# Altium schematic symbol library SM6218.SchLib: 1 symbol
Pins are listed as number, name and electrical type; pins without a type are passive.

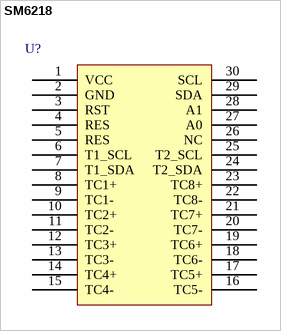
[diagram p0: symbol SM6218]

## SM6218
designator U?
footprint SM6218
pins: 1 VCC, 2 GND, 3 RST, 4 RES, 5 RES, 6 T1_SCL, 7 T1_SDA, 8 TC1+, 9 TC1-, 10 TC2+, 11 TC2-, 12 TC3+, 13 TC3-, 14 TC4+, 15 TC4-, 16 TC5-, 17 TC5+, 18 TC6-, 19 TC6+, 20 TC7-, 21 TC7+, 22 TC8-, 23 TC8+, 24 T2_SDA, 25 T2_SCL, 26 NC, 27 A0, 28 A1, 29 SDA, 30 SCL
